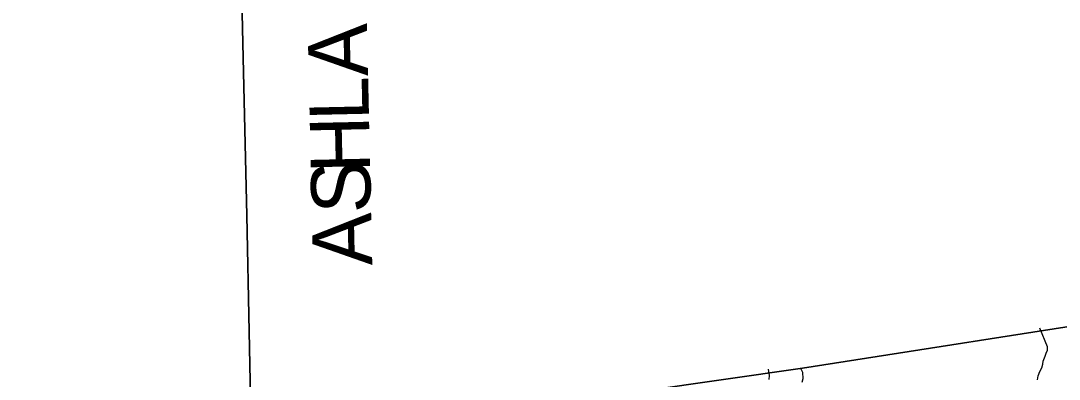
# Model space of a CAD drawing. Extents: x 1759416 to 2214760, y 252598 to 1116833.
# Drawn here: x 2009968 to 2027466, y 931768 to 937811 of the extents above; entities that cross this region are included whole.
import ezdxf

# ---------------------------------------------------------------- set-up
doc = ezdxf.new("R2010")
doc.units = 0
for name, color, linetype in [('GM_X_Adjacent_County', 7, 'Continuous'), ('GM_X_Adjacent_County_Text', 7, 'Continuous'), ('GM_X_County', 7, 'Continuous'), ('GM_X_County_Road', 7, 'Continuous'), ('GM_X_Minor_River', 7, 'Continuous'), ('GM_X_Township', 7, 'Continuous')]:
    doc.layers.add(name, color=color, linetype=linetype)

msp = doc.modelspace()

# ---------------------------------------------------------------- linework, layer by layer
at = {"layer": 'GM_X_Adjacent_County'}
for points in [[(2013620, 941438), (2013715, 937187), (2013775, 934527), (2013857, 930619), (2011234, 930213), (2008943, 929865), (2007573, 929691), (2003242, 929141), (2002301, 929187), (1997884, 929140)], [(2046190, 941524), (2046230, 937601), (2046240, 936623), (2046246, 935556), (2043971, 935214), (2038391, 934329), (2034945, 933785), (2031637, 933277), (2031111, 933198), (2030108, 933014), (2028816, 932841), (2023140, 931954), (2017738, 931179), (2016684, 931060), (2016073, 930958), (2013857, 930619), (2013775, 934527), (2013715, 937187), (2013620, 941438)]]:
    msp.add_lwpolyline(points, dxfattribs=at)
at = {"layer": 'GM_X_County'}
msp.add_lwpolyline([(1997884, 929140), (2002301, 929187), (2003242, 929141), (2007573, 929691), (2008943, 929865), (2011234, 930213), (2013857, 930619), (2016073, 930958), (2016684, 931060), (2017738, 931179), (2023140, 931954), (2028816, 932841)], dxfattribs=at)
at = {"layer": 'GM_X_County_Road'}
msp.add_lwpolyline([(2023137, 931720), (2023149, 931782), (2023147, 931879), (2023114, 931948)], dxfattribs=at)
at = {"layer": 'GM_X_Minor_River'}
for points in [[(2027098, 931756), (2027110, 931826), (2027140, 931898), (2027174, 931958), (2027188, 932020), (2027194, 932070), (2027228, 932154), (2027248, 932206), (2027266, 932258), (2027270, 932312), (2027137, 932629)], [(2022564, 931935), (2022577, 931829), (2022575, 931765)]]:
    msp.add_lwpolyline(points, dxfattribs=at)
at = {"layer": 'GM_X_Township'}
msp.add_lwpolyline([(2007080, 920037), (2007121, 920797), (2007263, 923436), (2007268, 923555), (2007337, 924671), (2007371, 925406), (2007440, 926818), (2007496, 927865), (2007522, 928477), (2007563, 929430), (2007573, 929691), (2008943, 929865), (2011234, 930213), (2013857, 930619), (2016073, 930958), (2016684, 931060), (2017738, 931179), (2023140, 931954), (2028816, 932841)], dxfattribs=at)

# ---------------------------------------------------------------- texts
at = {"layer": 'GM_X_Adjacent_County_Text'}
for s, rotation, p in [('A', 91.2618, (2015820, 936882)), ('L', 91.2618, (2015837, 936135)), ('H', 91.2617, (2015856, 935253)), ('S', 91.2617, (2015871, 934573)), ('A', 91.2618, (2015891, 933691))]:
    msp.add_text(s, height=1000, rotation=rotation, dxfattribs=at).set_placement(p)

doc.saveas('drawing.dxf')
